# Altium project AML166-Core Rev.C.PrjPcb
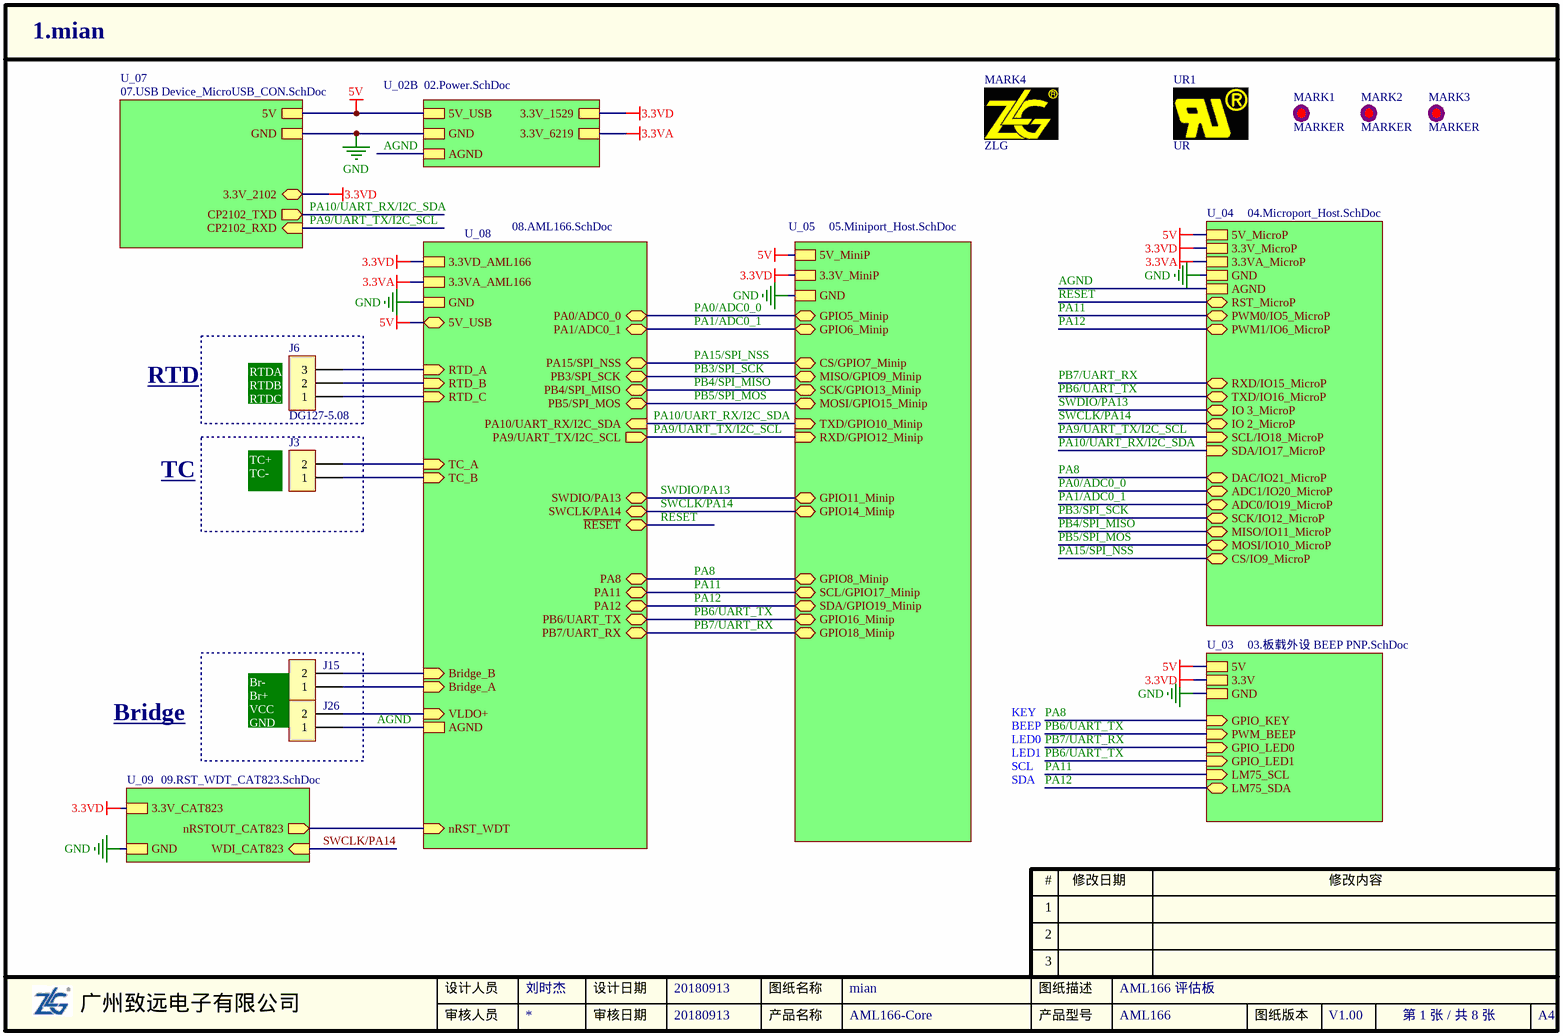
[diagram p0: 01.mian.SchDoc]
8 sheets, 138 parts. Net scope: hierarchical (ports join the sheet entries above them; power ports are global).
Board file: AML166-Core Rev.C.PcbDoc
Sheets:
  01.mian.SchDoc
    U_08 = 08.AML166.SchDoc
    U_05 = 05.Miniport_Host.SchDoc
    U_04 = 04.Microport_Host.SchDoc
    U_03 = 03.板载外设 BEEP PNP.SchDoc
    U_02B = 02.Power.SchDoc
    U_09 = 09.RST_WDT_CAT823.SchDoc
    U_07 = 07.USB Device_MicroUSB_CON.SchDoc

## Sheet 01.mian.SchDoc
size A4; Author: 刘时杰; CompanyName: 广州致远电子有限公司; DocumentNumber: 1; SheetNumber: 1; SheetTotal: 8; PageSetup: Record=PageOptions|CenterHorizontal=True|CenterVertical=True|PrintScale=1.00|XCorrection=1.00|YCorrection=1.00|PrintKind=0|BorderSize=5000000|LeftOffset=0|BottomOffset=0|Orientation=2|PaperLength=1000|PaperWidth=1000|Scale=100|PaperSource=7|PrintQuality=600|MediaType=1|DitherType=10|PaperKind=A4|PrintScaleMode=1; DesignDate: 20180913; CheckDate: 20180913; SheetName: mian; SheetVersion: V1.00; SheetDescription: AML166 评估板; ProductName: AML166-Core; ProductModel: AML166

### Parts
J3  (no value)  [CON508P810W130D15S-2DIP]
J6  DG127-5.08  [CON508P1524L810W110D15S-3DIP]
J15  (no value)  [CON508P810W130D15S-2DIP]
J26  (no value)  [CON508P810W130D15S-2DIP]
MARK1  MARKER  [MARKER-C-1.0M]  (no BOM)
MARK2  MARKER  [MARKER-C-1.0M]  (no BOM)
MARK3  MARKER  [MARKER-C-1.0M]  (no BOM)
MARK4  ZLG  [ZLG0.7]  (no BOM)
UR1  UR  [ZY_UR-3X2]  (no BOM)

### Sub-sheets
U_02B = 02.Power.SchDoc: GND, 5V_USB, 3.3V_1529, 3.3V_6219, AGND
U_03 = 03.板载外设 BEEP PNP.SchDoc: GND, 3.3V, PWM_BEEP (in), GPIO_LED0 (in), GPIO_LED1 (in), 5V, LM75_SCL (in), LM75_SDA (bidir), GPIO_KEY (in)
U_04 = 04.Microport_Host.SchDoc: GND, 3.3V_MicroP, AGND, 5V_MicroP, 3.3VA_MicroP, RXD/IO15_MicroP (bidir), TXD/IO16_MicroP (bidir), MOSI/IO10_MicroP (bidir), SCK/IO12_MicroP (bidir), MISO/IO11_MicroP (bidir), IO 3_MicroP (bidir), IO 2_MicroP (bidir), PWM1/IO6_MicroP (bidir), PWM0/IO5_MicroP (bidir), SDA/IO17_MicroP (in), SCL/IO18_MicroP (in), ADC1/IO20_MicroP (bidir), ADC0/IO19_MicroP (bidir), DAC/IO21_MicroP (bidir), RST_MicroP (bidir), CS/IO9_MicroP (bidir)
U_05 = 05.Miniport_Host.SchDoc: GND, 3.3V_MiniP, 5V_MiniP, MISO/GPIO9_Minip (bidir), GPIO5_Minip (bidir), MOSI/GPIO15_Minip (bidir), SCK/GPIO13_Minip (bidir), GPIO11_Minip (bidir), CS/GPIO7_Minip (bidir), GPIO14_Minip (bidir), GPIO6_Minip (bidir), RXD/GPIO12_Minip (in), TXD/GPIO10_Minip (in), GPIO8_Minip (bidir), GPIO16_Minip (bidir), SDA/GPIO19_Minip (bidir), SCL/GPIO17_Minip (bidir), GPIO18_Minip (bidir)
U_07 = 07.USB Device_MicroUSB_CON.SchDoc: 5V, GND, CP2102_TXD (out), CP2102_RXD (in), 3.3V_2102
U_08 = 08.AML166.SchDoc: nRST_WDT (in), 3.3VD_AML166, PA10/UART_RX/I2C_SDA (in), PA15/SPI_NSS (bidir), PA0/ADC0_0 (bidir), PA1/ADC0_1 (bidir), PA9/UART_TX/I2C_SCL (out), PB3/SPI_SCK (bidir), PB5/SPI_MOS (bidir), PA11 (bidir), PA12 (bidir), PB7/UART_RX (bidir), PB4/SPI_MISO (bidir), PA8 (bidir), PB6/UART_TX (bidir), GND, RTD_A (in), RTD_B (in), RTD_C (in), TC_A (in), TC_B (in), AGND, SWDIO/PA13 (bidir), SWCLK/PA14 (bidir), ~{RESET} (bidir), 3.3VA_AML166, Bridge_A (in), Bridge_B (in), VLDO+ (in), 5V_USB
U_09 = 09.RST_WDT_CAT823.SchDoc: GND, 3.3V_CAT823, WDI_CAT823 (in), nRSTOUT_CAT823 (out)

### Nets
3.3VA: sheet U_08/3.3VA_AML166, sheet U_04/3.3VA_MicroP, sheet U_02B/3.3V_6219  [project net 3.3V_6219]
3.3VD: sheet U_08/3.3VD_AML166, sheet U_05/3.3V_MiniP, sheet U_04/3.3V_MicroP, sheet U_03/3.3V, sheet U_02B/3.3V_1529, sheet U_09/3.3V_CAT823, sheet U_07/3.3V_2102  [project net 3.3V]
5V: sheet U_08/5V_USB, sheet U_05/5V_MiniP, sheet U_04/5V_MicroP, sheet U_03/5V, sheet U_02B/5V_USB, sheet U_07/5V
AGND: J26.1 ; sheet U_08/GND, sheet U_08/AGND, sheet U_05/GND, sheet U_04/GND, sheet U_04/AGND, sheet U_03/GND, sheet U_02B/GND, sheet U_02B/AGND, sheet U_09/GND, sheet U_07/GND  [also labelled GND]
ADC1_0: J15.1 ; sheet U_08/Bridge_A
ADC1_1: J15.2 ; sheet U_08/Bridge_B
nRST_WDT: sheet U_08/nRST_WDT, sheet U_09/nRSTOUT_CAT823
PA0/ADC0_0: sheet U_08/PA0/ADC0_0, sheet U_05/GPIO5_Minip, sheet U_04/ADC1/IO20_MicroP  [project net ADC1/IO20_MicroP]
PA1/ADC0_1: sheet U_08/PA1/ADC0_1, sheet U_05/GPIO6_Minip, sheet U_04/ADC0/IO19_MicroP  [project net ADC0/IO19_MicroP]
PA8: sheet U_08/PA8, sheet U_05/GPIO8_Minip, sheet U_04/DAC/IO21_MicroP, sheet U_03/GPIO_KEY  [project net DAC/IO21_MicroP]
PA9/UART_TX/I2C_SCL: sheet U_08/PA9/UART_TX/I2C_SCL, sheet U_05/RXD/GPIO12_Minip, sheet U_04/SCL/IO18_MicroP, sheet U_07/CP2102_RXD
PA10/UART_RX/I2C_SDA: sheet U_08/PA10/UART_RX/I2C_SDA, sheet U_05/TXD/GPIO10_Minip, sheet U_04/SDA/IO17_MicroP, sheet U_07/CP2102_TXD
PA11: sheet U_08/PA11, sheet U_05/SCL/GPIO17_Minip, sheet U_04/PWM0/IO5_MicroP, sheet U_03/LM75_SCL  [project net LM75_SCL]
PA12: sheet U_08/PA12, sheet U_05/SDA/GPIO19_Minip, sheet U_04/PWM1/IO6_MicroP, sheet U_03/LM75_SDA  [project net LM75_SDA]
PA15/SPI_NSS: sheet U_08/PA15/SPI_NSS, sheet U_05/CS/GPIO7_Minip, sheet U_04/CS/IO9_MicroP  [project net CS/GPIO7_Minip]
PB3/SPI_SCK: sheet U_08/PB3/SPI_SCK, sheet U_05/MISO/GPIO9_Minip, sheet U_04/SCK/IO12_MicroP  [project net MISO/GPIO9_Minip]
PB4/SPI_MISO: sheet U_08/PB4/SPI_MISO, sheet U_05/SCK/GPIO13_Minip, sheet U_04/MISO/IO11_MicroP  [project net MISO/IO11_MicroP]
PB5/SPI_MOS: sheet U_08/PB5/SPI_MOS, sheet U_05/MOSI/GPIO15_Minip, sheet U_04/MOSI/IO10_MicroP  [project net MOSI/GPIO15_Minip]
PB6/UART_TX: sheet U_08/PB6/UART_TX, sheet U_05/GPIO16_Minip, sheet U_04/TXD/IO16_MicroP, sheet U_03/PWM_BEEP, sheet U_03/GPIO_LED1  [project net GPIO16_Minip]
PB7/UART_RX: sheet U_08/PB7/UART_RX, sheet U_05/GPIO18_Minip, sheet U_04/RXD/IO15_MicroP, sheet U_03/GPIO_LED0  [project net GPIO18_Minip]
~{RESET}: sheet U_08/~{RESET}, sheet U_04/RST_MicroP
RTD_A: J6.3 ; sheet U_08/RTD_A
RTD_B: J6.2 ; sheet U_08/RTD_B
RTD_C: J6.1 ; sheet U_08/RTD_C
SWCLK/PA14: sheet U_08/SWCLK/PA14, sheet U_05/GPIO14_Minip, sheet U_04/IO 2_MicroP, sheet U_09/WDI_CAT823  [project net GPIO14_Minip]
SWDIO/PA13: sheet U_08/SWDIO/PA13, sheet U_05/GPIO11_Minip, sheet U_04/IO 3_MicroP  [project net GPIO11_Minip]
TC_A: J3.2 ; sheet U_08/TC_A
TC_B: J3.1 ; sheet U_08/TC_B
VLDO: J26.2 ; sheet U_08/VLDO+

Not connected (* = marked no-connect by the designer): MARK1 0; MARK2 0; MARK3 0

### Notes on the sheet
- RTD
- (near J6) RTDA
  RTDB
  RTDC
- TC
- (near J3) TC+
  TC-
- KEY
- Bridge
- Br-
  Br+
  VCC
  GND
- BEEP
- LED0
- LED1
- SCL
- SDA

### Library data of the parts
J3 J15 J26 = 1.10.06.0070: DG127-5.08-02P-14-00AH,180°,绿色,DEGSON,RoHS; 名称: 端子; 贴片和直插: THT; PCB备注: xhm-lq-wyy-150126; 器件优选方案: 正常状态，可以选用
J6 = 19.04.00251: DG127-5.08-03P-14-00AH,180°,绿色,THT; 名称: 端子; PCB备注: 180925 yyf

## Sheet 08.AML166.SchDoc
size A3; CheckedBy: <审核人员>; Author: 刘时杰; DocumentNumber: 7; SheetNumber: 7; SheetTotal: 8; PageSetup: Record=PageOptions|CenterHorizontal=True|CenterVertical=True|PrintScale=1.00|XCorrection=1.00|YCorrection=1.00|PrintKind=0|BorderSize=5000000|LeftOffset=0|BottomOffset=0|Orientation=2|PaperLength=1000|PaperWidth=1000|Scale=100|PaperSource=7|PrintQuality=600|MediaType=1|DitherType=10|PaperKind=A4|PrintScaleMode=1; DesignDate: 20180913; CheckDate: <审核日期>; SheetName: AML166_ADC24; SheetVersion: <图纸版本>; SheetDescription: AML166评估24位ADC性能电路; ProductName: AML166; ProductModel: AML166-Core
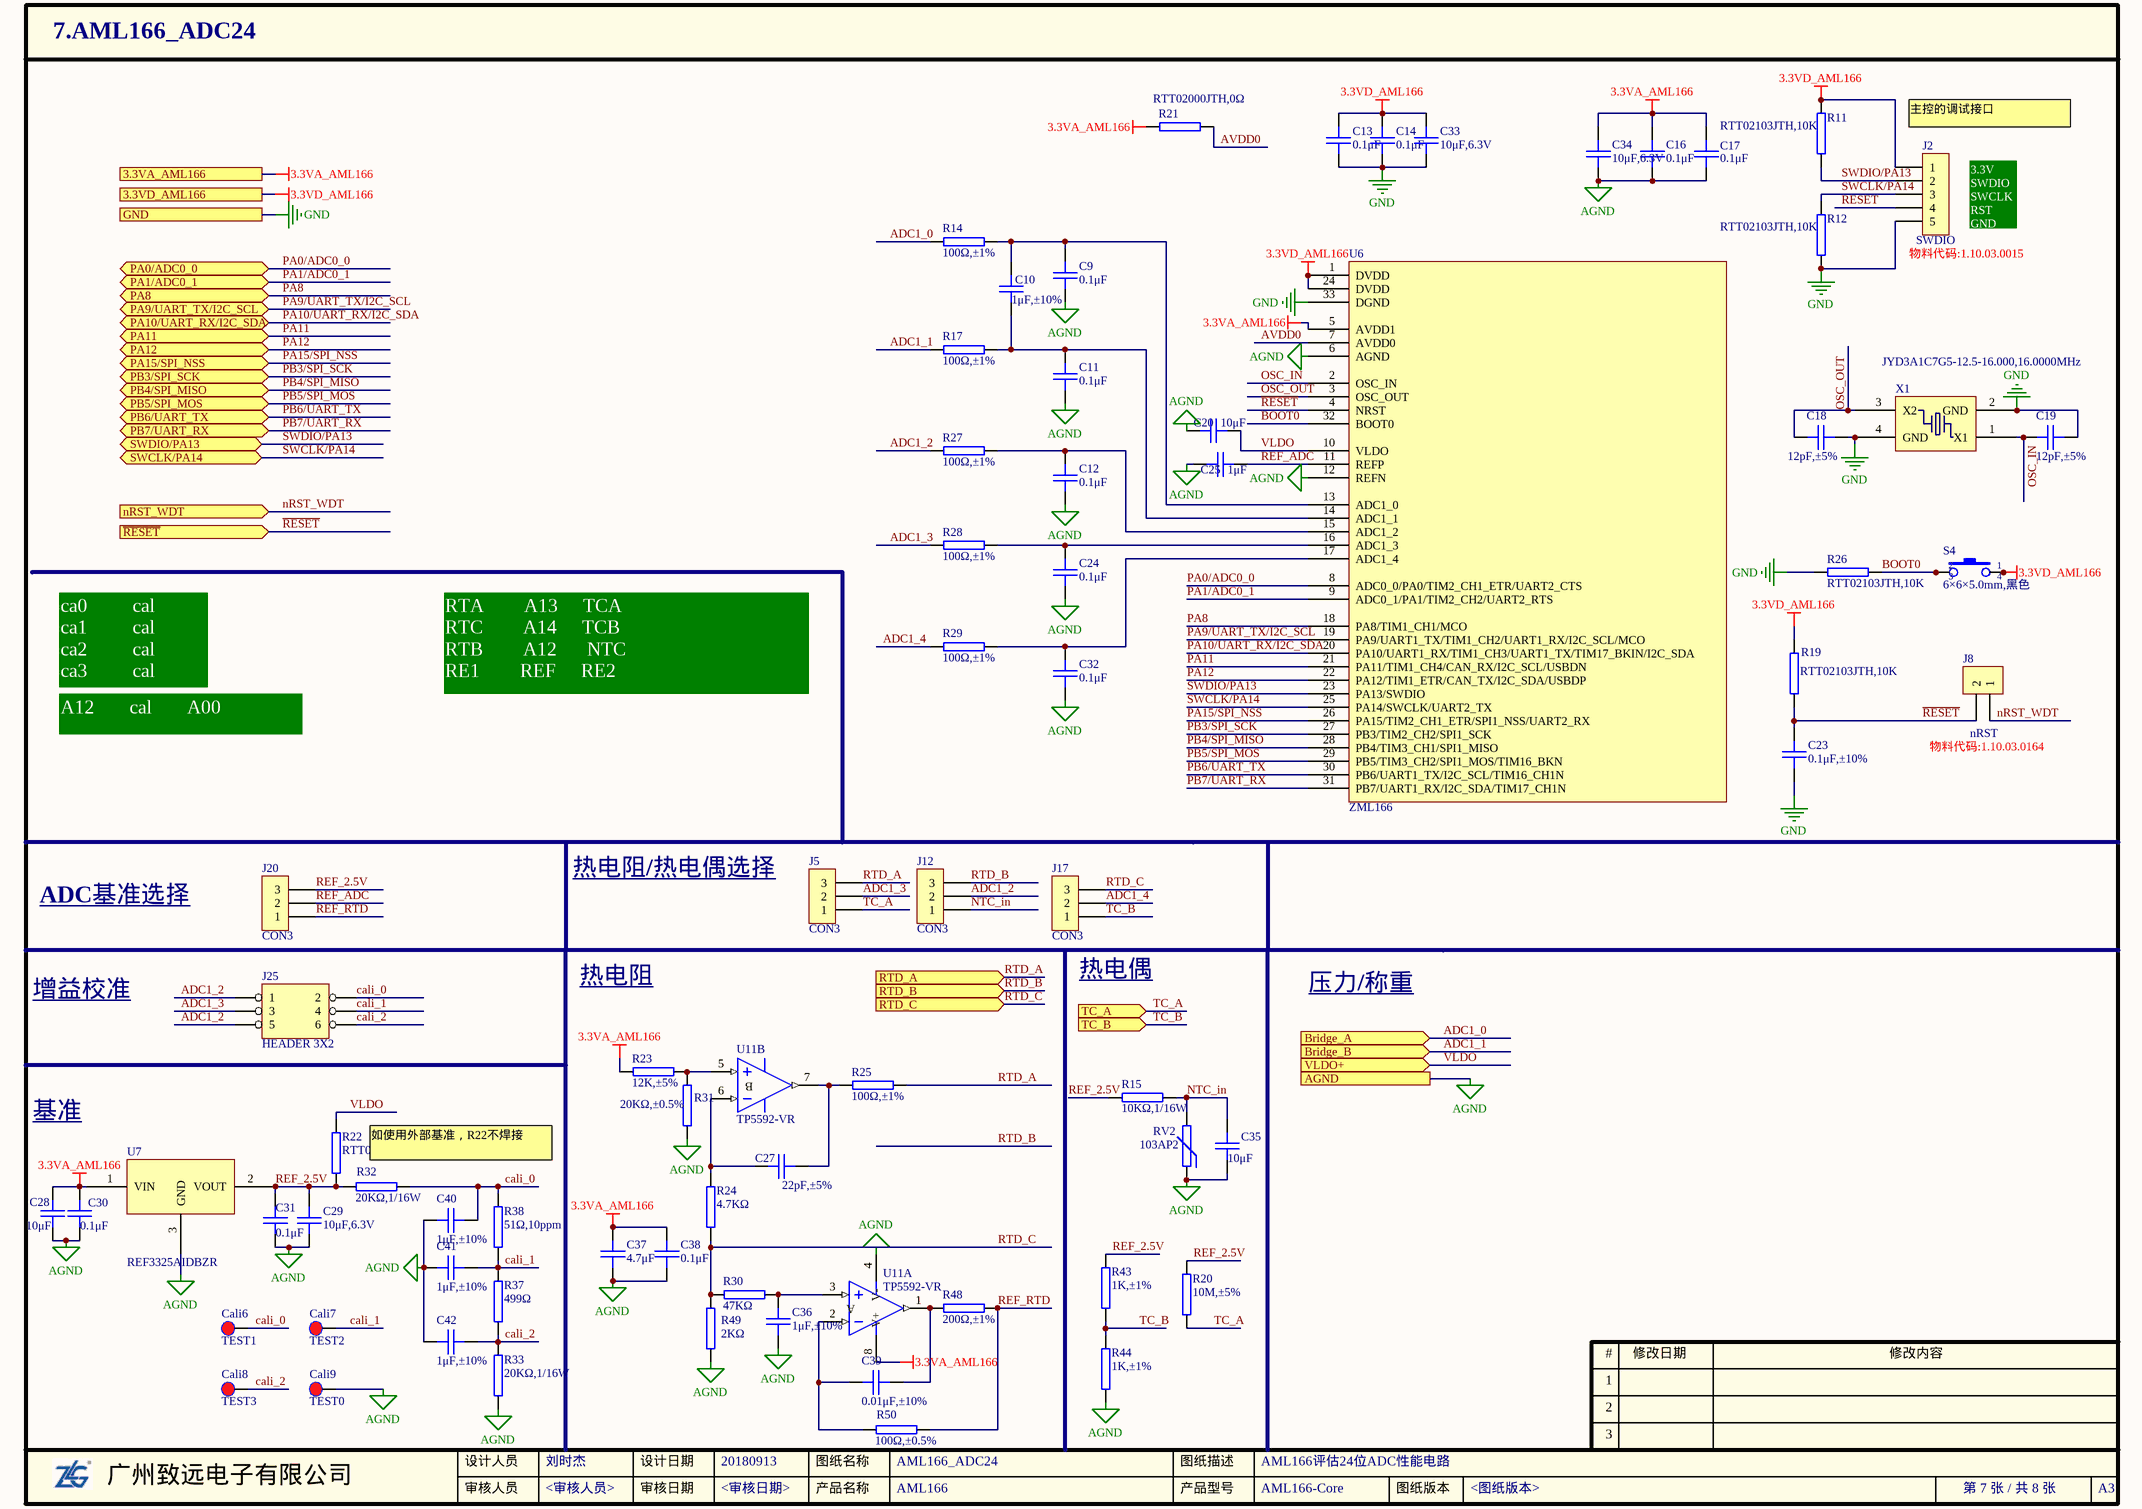
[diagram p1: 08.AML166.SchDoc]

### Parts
C9  0.1μF  [0402C]
C10  1μF,±10%  [0402C]
C11  0.1μF  [0402C]
C12  0.1μF  [0402C]
C13  0.1μF  [0402C]
C14  0.1μF  [0402C]
C16  0.1μF  [0402C]
C17  0.1μF  [0402C]
C18  12pF,±5%  [0402C]
C19  12pF,±5%  [0402C]
C20  10μF  [0603C]
C23  0.1μF,±10%  [0402C]
C24  0.1μF  [0402C]
C25  1μF  [0402C]
C27  22pF,±5%  [0402C]
C28  10μF  [0603C]
C29  10μF,6.3V  [0603C]
C30  0.1μF  [0402C]
C31  0.1μF  [0402C]
C32  0.1μF  [0402C]
C33  10μF,6.3V  [0603C]
C34  10μF,6.3V  [0603C]
C35  10μF  [0603C]
C36  1μF,±10%  [0402C]
C37  4.7μF  [0402C]
C38  0.1μF  [0402C]
C39  0.01μF,±10%  [0402C]
C40  1μF,±10%  [0402C]
C41  1μF,±10%  [0402C]
C42  1μF,±10%  [0402C]
Cali6  TEST1  [PAD-25/40]  (no BOM)
Cali7  TEST2  [PAD-25/40]  (no BOM)
Cali8  TEST3  [PAD-25/40]  (no BOM)
Cali9  TEST0  [PAD-25/40]  (no BOM)
J2  SWDIO  [SIP-5-2.54-6.0-R90]
J5  CON3  [SIP-3-2.54]
J8  nRST  [SIP-2-2.54]
J12  CON3  [SIP-3-2.54]
J17  CON3  [SIP-3-2.54]
J20  CON3  [SIP-3-2.54]
J25  HEADER 3X2  [IDC-6-2.54]
R11  RTT02103JTH,10K  [0402R]
R12  RTT02103JTH,10K  [0402R]
R14  100Ω,±1%  [0402R]
R15  10KΩ,1/16W  [0603R]
R17  100Ω,±1%  [0402R]
R19  RTT02103JTH,10K  [0402R]
R20  10M,±5%  [0402R]
R21  RTT02000JTH,0Ω  [0402R]
R22  RTT02000JTH,0Ω  [0402R]  (no BOM)
R23  12K,±5%  [0402R]
R24  4.7KΩ  [0603R]
R25  100Ω,±1%  [0402R]
R26  RTT02103JTH,10K  [0402R]
R27  100Ω,±1%  [0402R]
R28  100Ω,±1%  [0402R]
R29  100Ω,±1%  [0402R]
R30  47KΩ  [0603R]
R31  20KΩ,±0.5%  [0402R]
R32  20KΩ,1/16W  [0603R]
R33  20KΩ,1/16W  [0603R]
R37  499Ω  [0603R]
R38  51Ω,10ppm  [0603R]
R43  1K,±1%  [0402R]
R44  1K,±1%  [0402R]
R48  200Ω,±1%  [0402R]
R49  2KΩ  [0603R]
R50  100Ω,±0.5%  [0402R]
RV2  103AP2  [RESRR254W35L380T260H850P]
S4  value 6×6×5.0mm,黑色  [KEY-6S]  (hidden comment: SW-PB4P)
U6  ZML166  [QFN50P500X500X85-33N]
U7  REF3325AIDBZR  [SOT-23]
U11  TP5592-VR  [SOP65P490X120-8N]  (parts A,B of 2)
X1  JYD3A1C7G5-12.5-16.000,16.0000MHz  [OSCCC250X320X80-4N]

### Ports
3.3VA_AML166, 3.3VD_AML166, AGND, Bridge_A (in), Bridge_B (in), GND, nRST_WDT (in), PA0/ADC0_0 (bidir), PA1/ADC0_1 (bidir), PA8 (bidir), PA9/UART_TX/I2C_SCL (bidir), PA10/UART_RX/I2C_SDA (bidir), PA11 (bidir), PA12 (bidir), PA15/SPI_NSS (bidir), PB3/SPI_SCK (bidir), PB4/SPI_MISO (bidir), PB5/SPI_MOS (bidir), PB6/UART_TX (bidir), PB7/UART_RX (bidir), RTD_A (in), RTD_B (in), RTD_C (in), SWCLK/PA14 (bidir), SWDIO/PA13 (bidir), TC_A (in), TC_B (in), VLDO+ (in), ~{RESET} (in)

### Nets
3.3VA_AML166: C16.1 C17.1 C28.2 C30.1 C34.2 C37.1 C38.1 R21.1 R23.1 U6.5(AVDD1) U7.1(VIN) U11.8(V+) ; port 3.3VA_AML166  [project net 3.3V_6219]
3.3VD_AML166: C13.1 C14.1 C33.2 J2.1 R11.2 R19.1 S4.1 S4.4 U6.1(DVDD) U6.24(DVDD) ; port 3.3VD_AML166  [project net 3.3V]
AGND: C9.2 C11.2 C12.2 C13.2 C14.2 C16.2 C17.2 C18.1 C19.2 C20.2 C23.2 C24.2 C25.1 C28.1 C29.1 C30.2 C31.2 C32.2 C33.1 C34.1 C35.1 C36.2 C37.2 C38.2 C40.1 C41.1 C42.1 Cali9.1 J2.5 R12.1 R26.2 R31.1 R33.2 R44.2 R49.1 RV2.1 U6.6(AGND) U6.12(REFN) U6.33(DGND) U7.3(GND) U11.4(V-) X1.2(GND) X1.4(GND) ; port GND, port AGND  [also labelled GND]
ADC1_0: R14.1 ; port Bridge_A
ADC1_1: R17.1 ; port Bridge_B
ADC1_2: J12.2 J25.1 J25.5 R27.1
ADC1_3: J5.2 J25.3 R28.1
ADC1_4: J17.2 R29.1
AVDD0: R21.2 U6.7(AVDD0)
BOOT0: R26.1 S4.2 S4.3 U6.32(BOOT0)
cali_0: C40.2 Cali6.1 J25.2 R32.1 R38.1
cali_1: C41.2 Cali7.1 J25.4 R37.2 R38.2
cali_2: C42.2 Cali8.1 J25.6 R33.1 R37.1
nRST_WDT: J8.1 ; port nRST_WDT
NTC_in: C35.2 J12.1 R15.2 RV2.2
OSC_IN: C19.1 U6.2(OSC_IN) X1.1(X1)
OSC_OUT: C18.2 U6.3(OSC_OUT) X1.3(X2)
PA0/ADC0_0: U6.8(ADC0_0/PA0/TIM2_CH1_ETR/UART2_CTS) ; port PA0/ADC0_0  [project net ADC1/IO20_MicroP]
PA1/ADC0_1: U6.9(ADC0_1/PA1/TIM2_CH2/UART2_RTS) ; port PA1/ADC0_1  [project net ADC0/IO19_MicroP]
PA8: U6.18(PA8/TIM1_CH1/MCO) ; port PA8  [project net DAC/IO21_MicroP]
PA9/UART_TX/I2C_SCL: U6.19(PA9/UART1_TX/TIM1_CH2/UART1_RX/I2C_SCL/MCO) ; port PA9/UART_TX/I2C_SCL
PA10/UART_RX/I2C_SDA: U6.20(PA10/UART1_RX/TIM1_CH3/UART1_TX/TIM17_BKIN/I2C_SDA) ; port PA10/UART_RX/I2C_SDA
PA11: U6.21(PA11/TIM1_CH4/CAN_RX/I2C_SCL/USBDN) ; port PA11  [project net LM75_SCL]
PA12: U6.22(PA12/TIM1_ETR/CAN_TX/I2C_SDA/USBDP) ; port PA12  [project net LM75_SDA]
PA15/SPI_NSS: U6.26(PA15/TIM2_CH1_ETR/SPI1_NSS/UART2_RX) ; port PA15/SPI_NSS  [project net CS/GPIO7_Minip]
PB3/SPI_SCK: U6.27(PB3/TIM2_CH2/SPI1_SCK) ; port PB3/SPI_SCK  [project net MISO/GPIO9_Minip]
PB4/SPI_MISO: U6.28(PB4/TIM3_CH1/SPI1_MISO) ; port PB4/SPI_MISO  [project net MISO/IO11_MicroP]
PB5/SPI_MOS: U6.29(PB5/TIM3_CH2/SPI1_MOS/TIM16_BKN) ; port PB5/SPI_MOS  [project net MOSI/GPIO15_Minip]
PB6/UART_TX: U6.30(PB6/UART1_TX/I2C_SCL/TIM16_CH1N) ; port PB6/UART_TX  [project net GPIO16_Minip]
PB7/UART_RX: U6.31(PB7/UART1_RX/I2C_SDA/TIM17_CH1N) ; port PB7/UART_RX  [project net GPIO18_Minip]
~{RESET}: C23.1 J2.4 J8.2 R19.2 U6.4(NRST) ; port ~{RESET}
REF_2.5V: C29.2 C31.1 J20.3 R15.1 R20.2 R22.1 R32.2 R43.2 U7.2(VOUT)
REF_ADC: C25.2 J20.2 U6.11(REFP)
REF_RTD: J20.1 R48.2 R50.1
RTD_A: J5.3 R25.2 ; port RTD_A
RTD_B: J12.3 ; port RTD_B
RTD_C: J17.3 R24.1 R30.1 R49.2 ; port RTD_C
SWCLK/PA14: J2.3 R12.2 U6.25(PA14/SWCLK/UART2_TX) ; port SWCLK/PA14  [project net GPIO14_Minip]
SWDIO/PA13: J2.2 R11.1 U6.23(PA13/SWDIO) ; port SWDIO/PA13  [project net GPIO11_Minip]
TC_A: J5.1 R20.1 ; port TC_A
TC_B: J17.1 R43.1 R44.1 ; port TC_B
VLDO: C20.1 R22.2 U6.10(VLDO) ; port VLDO+
NetC9_1: C9.1 C10.1 R14.2 U6.13(ADC1_0)
NetC10_2: C10.2 C11.1 R17.2 U6.14(ADC1_1)
NetC12_1: C12.1 R27.2 U6.15(ADC1_2)
NetC24_1: C24.1 R28.2 U6.16(ADC1_3)
NetC27_1: C27.1 R24.2 U11.6(IN-)
NetC27_2: C27.2 R25.1 U11.7(OUT)
NetC32_1: C32.1 R29.2 U6.17(ADC1_4)
NetC36_1: C36.1 R30.2 U11.3(IN+)
NetC39_1: C39.1 R50.2 U11.2(IN-)
NetC39_2: C39.2 R48.1 U11.1(OUT)
NetR23_2: R23.2 R31.2 U11.5(IN+)

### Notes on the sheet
- (near J2) 主控的调试接口
- (near J2) 3.3V
  SWDIO
  SWCLK
  RST
  GND
- (near J2) 物料代码:1.10.03.0015
- ca0         cal
  ca1         cal
  ca2         cal
  ca3         cal
- RTA        A13     TCA
  RTC        A14     TCB
  RTB        A12      NTC
  RE1        REF     RE2
- A12       cal       A00
- (near J8) 物料代码:1.10.03.0164
- ADC基准选择
- 热电阻/热电偶选择
- 热电阻
- (near J17) 热电偶
- 压力/称重
- 增益校准
- 基准
- 如使用外部基准，R22不焊接

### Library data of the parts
C9 C11-C14 C16 C17 C24 C30-C32 C38 = 1.02.17.0118: GCM155R71E104KE02D,0.1μF,±10%,25V,X7R,0402,muRata,RoHS; 名称: 电容; 封装: 0402; 贴片和直插: SMT; PCB备注: 161012yjh; 器件优选方案: 正常状态，可以选用
C10 C25 C36 C40-C42 = 1.02.17.0092: GRM155R61C105KA12D,1μF,±10% ,16V,X5R,0402,muRata,RoHS; 名称: 电容; 封装: 0402; 贴片和直插: SMT; PCB备注: 无数据手册，依据采购部提供的信息添加的封装。; 器件优选方案: 正常状态，可以选用
C18 C19 = 1.02.17.0018: GRM1555C1H120JA01D,12pF,±5%,50V,C0G,0402,muRata,RoHS; 名称: 电容; 封装: 0402; 设备封装名称: C0402_12PF_COG_50V_5%; 贴片和直插: SMT; 器件优选方案: 正常状态，可以选用
C20 C28 C29 C33-C35 = 1.02.01.0065: 10μF,6.3V,X5R,GRM188R60J106M****,0603,Murata,RoHS; 名称: 电容; 封装: 0603; 贴片和直插: SMT; 器件优选方案: 正常状态，可以选用
C23 = 1.02.17.0006: GRM155R71C104KA88D,0.1μF,±10%,16V,X7R,0402,muRata,RoHS; 名称: 电容; 封装: 0402; 设备封装名称: C0402_0.1uF_X7R_16V_10%; 贴片和直插: SMT; 器件优选方案: 正常状态，可以选用
C27 = 1.02.17.0036: GRM1555C1H220JA01D,22pF,±5%,50V,C0G,0402,muRata,RoHS; 名称: 电容; 封装: 0402; 设备封装名称: C0402_22PF_NPO_50V_5%; 贴片和直插: SMT; 器件优选方案: 正常状态，可以选用
C37 = 1.02.17.0073: GRM155R60J475ME87D,4.7μF,±20%,6.3V,X5R,0402,muRata,RoHS; 名称: 电容; 封装: 0402; 贴片和直插: SMT; 器件优选方案: 正常状态，可以选用
C39 = 1.02.17.0019: GRM155R71H103KA88D,0.01μF,±10%,50V,X7R,0402,muRata,RoHS; 名称: 电容; 封装: 0402; 设备封装名称: C0402_0.01uF_X7R_50V_10%; 贴片和直插: SMT; 器件优选方案: 正常状态，可以选用
Cali6-Cali9 = TEST-DOT
J2 = CON5: Connector; 物料代码: 1.10.03.0015
J5 J12 J17 J20 = CON3: Connector
J8 = CON2: Connector; 物料代码: 1.10.03.0164
R11 R12 R19 R26 = 1.01.17.0006: RTT02103JTH,10K,±5%,0402,RALEC,RoHS; 名称: 电阻; 封装: 0402; 设备封装名称: R0402_10K; 贴片和直插: SMT; 器件优选方案: 正常状态，可以选用
R14 R17 R25 R27-R29 = 1.01.17.0029: 100Ω,±1%,0402,RALEC,RoHS; 名称: 电阻; 封装: 0402; 设备封装名称: R0402_100R_1%; 贴片和直插: SMT; 器件优选方案: 正常状态，可以选用
R15 = 1.01.01.0192: 10KΩ,1/16W,10PPM/℃,±0.1%,0603,Viking,RoHS; 名称: 电阻; 封装: 0603; 设备封装名称: R0603_10K_0.1%; 贴片和直插: SMT; 器件优选方案: 临时/偏门物料/不主推物料，谨慎选用
R20 = 1.01.17.0005: 10M,±5%,0402,RALEC,RoHS; 名称: 电阻; 封装: 0402; 设备封装名称: R0402_10M; 贴片和直插: SMT; 器件优选方案: 正常状态，可以选用
R21 R22 = 1.01.17.0004: RTT02000JTH,0Ω,±5%,0402,RALEC,RoHS; 名称: 电阻; 封装: 0402; 设备封装名称: R0402_0R; 贴片和直插: SMT; 器件优选方案: 正常状态，可以选用
R23 = 1.01.17.0035: 12K,±5%,0402,RALEC,RoHS; 名称: 电阻; 封装: 0402; 设备封装名称: R0402_12K; 贴片和直插: SMT; 器件优选方案: 正常状态，可以选用
R24 = 1.01.01.0045: 4.7KΩ,0603,*,RoHS; 名称: 电阻; 封装: 0603; 设备封装名称: R0603_4.7K; 厂商: Ralec; 贴片和直插: SMT; 器件优选方案: 正常状态，可以选用
R30 = 1.01.01.0060: 47KΩ,0603,*,RoHS; 名称: 电阻; 封装: 0603; 设备封装名称: R0603_47K; 厂商: Ralec; 贴片和直插: SMT; 器件优选方案: 正常状态，可以选用
R31 = 1.01.17.0053: 20KΩ,±0.5%,0402,RoHS; 名称: 电阻; 封装: 0402; 设备封装名称: R0402_20K_0.5%; 厂商: Ralec; 贴片和直插: SMT; 器件优选方案: 正常状态，可以选用
R32 R33 = 1.01.01.0207: 20KΩ,1/16W,10PPM/℃,±0.1%,0603,Viking,RoHS; 名称: 电阻; 封装: 0603; 贴片和直插: SMT; 器件优选方案: 临时/偏门物料/不主推物料，谨慎选用
R37 = 1.01.01.0155: 499Ω,RN731JTTD,4990B10,0603,KOA,RoHS; 名称: 电阻; 封装: 0603; 设备封装名称: R0603_499R_0.1%; 贴片和直插: SMT; 器件优选方案: 临时/偏门物料/不主推物料，谨慎选用
R38 = 1.01.01.0215: 51Ω,10ppm,±0.1%,AR03BTB0510,0603,Viking,RoHS; 名称: 电阻; 封装: 0603; 贴片和直插: SMT; 器件优选方案: 临时/偏门物料/不主推物料，谨慎选用
R43 R44 = 1.01.17.0016: 1K,±1%,0402,RALEC,RoHS; 名称: 电阻; 封装: 0402; 设备封装名称: R0402_1K_1%; 贴片和直插: SMT; 器件优选方案: 正常状态，可以选用
R48 = 1.01.17.0073: 200Ω,±1%,0402,RoHS; 名称: 电阻; 封装: 0402; 设备封装名称: R0402_200R_1%; 厂商: Ralec; 贴片和直插: SMT; 器件优选方案: 正常状态，可以选用
R49 = 1.01.01.0157: 2KΩ,RN731JTTD,2001B10,0603,KOA,RoHS; 名称: 电阻; 封装: 0603; 设备封装名称: R0603_2K_0.1%; 贴片和直插: SMT; 器件优选方案: 临时/偏门物料/不主推物料，谨慎选用
R50 = 1.01.17.0052: 100Ω,±0.5%,0402,RoHS; 名称: 电阻; 封装: 0402; 设备封装名称: R0402_100R_0.5%; 厂商: Ralec; 贴片和直插: SMT; 器件优选方案: 正常状态，可以选用
RV2 = 1.01.14.0020: 103AP2,SIP,semitec,RoHS; 名称: 热敏电阻(临时); 贴片和直插: THT; PCB备注: 171205CZY; 器件优选方案: 临时/偏门物料/不主推物料，谨慎选用
S4 = 1.09.01.0003: 6×6×5.0mm,黑色,SMD,,*; 名称: 轻触按键; 贴片和直插: SMT
U7 = 1.05.10.0334: REF3325AIDBZR,SOT-23,TI; 名称: 集成电路; 设备封装名称: SOT-23_REF3325AIDBZR; 贴片和直插: SMT; 器件优选方案: 量产物料,优先选用
U11 = 1.05.20.0102: TP5592-VR,MSOP-8,3PEAK,RoHS; 名称: 集成电路(临时); 贴片和直插: SMT; PCB备注: 170810lmd; 器件优选方案: 临时/偏门物料/不主推物料，谨慎选用
X1 = 1.07.03.0077: JYD3A1C7G5-12.5-16.000,16.0000MHz,±10ppm,12.5pF,-40~85℃,SMD3225,JYEG,RoHS; 名称: 晶体; 贴片和直插: SMT; PCB备注: 151225lmd171128ZW; 器件优选方案: 正常状态，可以选用

## Sheet 05.Miniport_Host.SchDoc
size A4; CheckedBy: <审核日期>; Author: 刘时杰; CompanyName: 广州致远电子有限公司; DocumentNumber: 5; SheetNumber: 5; SheetTotal: 8; PageSetup: Record=PageOptions|CenterHorizontal=True|CenterVertical=True|PrintScale=1.00|XCorrection=1.00|YCorrection=1.00|PrintKind=0|BorderSize=5000000|LeftOffset=0|BottomOffset=0|Orientation=2|PaperLength=1000|PaperWidth=1000|Scale=100|PaperSource=7|PrintQuality=600|MediaType=1|DitherType=10|PaperKind=A4|PrintScaleMode=1; DesignDate: 20180913; CheckDate: <审核人员>; SheetName: MiniPort接口; SheetVersion: V1.01; SheetDescription: MiniPort接口; productModel: AML166-Core; productName: AML166评估板
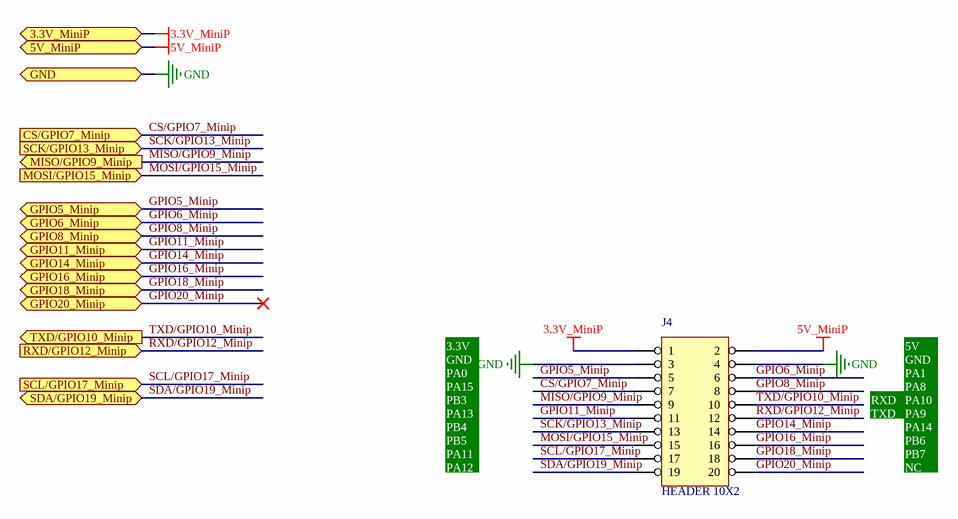
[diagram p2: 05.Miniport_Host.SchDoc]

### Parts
J4  HEADER 10X2  [IDC-20-2.54-R90]

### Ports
3.3V_MiniP, 5V_MiniP, CS/GPIO7_Minip (in), GND, GPIO5_Minip (bidir), GPIO6_Minip (bidir), GPIO8_Minip (bidir), GPIO11_Minip (bidir), GPIO14_Minip (bidir), GPIO16_Minip (bidir), GPIO18_Minip (bidir), GPIO20_Minip (bidir), MISO/GPIO9_Minip (out), MOSI/GPIO15_Minip (in), RXD/GPIO12_Minip (in), SCK/GPIO13_Minip (in), SCL/GPIO17_Minip (in), SDA/GPIO19_Minip (bidir), TXD/GPIO10_Minip (out)

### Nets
3.3V_MiniP: J4.1 ; port 3.3V_MiniP  [project net 3.3V]
5V_MiniP: J4.2 ; port 5V_MiniP  [project net 5V]
GND: J4.3 J4.4 ; port GND  [project net AGND]
CS/GPIO7_Minip: J4.7 ; port CS/GPIO7_Minip
GPIO5_Minip: J4.5 ; port GPIO5_Minip  [project net ADC1/IO20_MicroP]
GPIO6_Minip: J4.6 ; port GPIO6_Minip  [project net ADC0/IO19_MicroP]
GPIO8_Minip: J4.8 ; port GPIO8_Minip  [project net DAC/IO21_MicroP]
GPIO11_Minip: J4.11 ; port GPIO11_Minip
GPIO14_Minip: J4.14 ; port GPIO14_Minip
GPIO16_Minip: J4.16 ; port GPIO16_Minip
GPIO18_Minip: J4.18 ; port GPIO18_Minip
GPIO20_Minip: J4.20 ; port GPIO20_Minip
MISO/GPIO9_Minip: J4.9 ; port MISO/GPIO9_Minip
MOSI/GPIO15_Minip: J4.15 ; port MOSI/GPIO15_Minip
RXD/GPIO12_Minip: J4.12 ; port RXD/GPIO12_Minip  [project net PA9/UART_TX/I2C_SCL]
SCK/GPIO13_Minip: J4.13 ; port SCK/GPIO13_Minip  [project net MISO/IO11_MicroP]
SCL/GPIO17_Minip: J4.17 ; port SCL/GPIO17_Minip  [project net LM75_SCL]
SDA/GPIO19_Minip: J4.19 ; port SDA/GPIO19_Minip  [project net LM75_SDA]
TXD/GPIO10_Minip: J4.10 ; port TXD/GPIO10_Minip  [project net PA10/UART_RX/I2C_SDA]

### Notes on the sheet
- TXD
- RXD
- 3.3V
  GND
  PA0
  PA15
  PB3
  PA13
  PB4
  PB5
  PA11
  PA12
- 5V
  GND
  PA1
  PA8
  PA10
  PA9
  PA14
  PB6
  PB7
  NC

## Sheet 04.Microport_Host.SchDoc
size A4; CheckedBy: <审核日期>; Author: 刘时杰; CompanyName: 广州致远电子有限公司; DocumentNumber: 4; SheetNumber: 4; SheetTotal: 8; PageSetup: Record=PageOptions|CenterHorizontal=True|CenterVertical=True|PrintScale=1.00|XCorrection=1.00|YCorrection=1.00|PrintKind=0|BorderSize=5000000|LeftOffset=0|BottomOffset=0|Orientation=2|PaperLength=1000|PaperWidth=1000|Scale=100|PaperSource=7|PrintQuality=600|MediaType=1|DitherType=10|PaperKind=A4|PrintScaleMode=1; DesignDate: 20180913; CheckDate: <审核人员>; SheetName: MicroPort接口; SheetVersion: V1.01; SheetDescription: MicroPort接口; productModel: AML166-Core; productName: AML166评估板
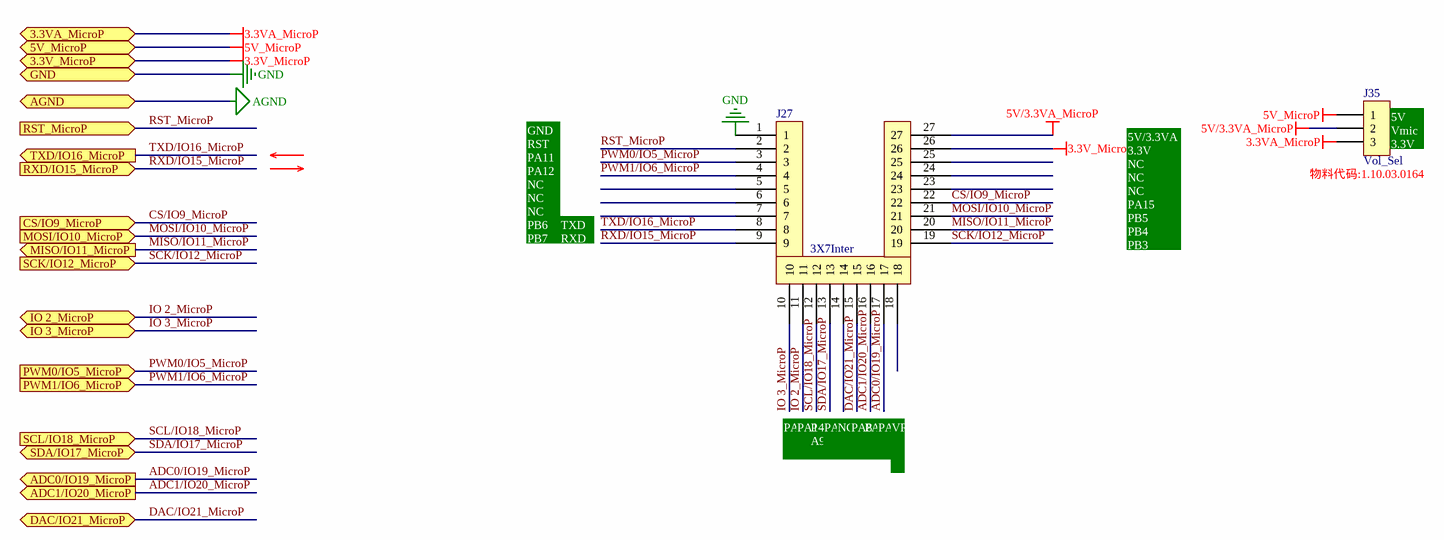
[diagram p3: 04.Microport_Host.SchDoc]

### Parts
J27  3X7Inter  [SIP-27 2.54C]
J35  Vol_Sel  [SIP-3-2.54]

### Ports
3.3V_MicroP, 3.3VA_MicroP, 5V_MicroP, ADC0/IO19_MicroP (out), ADC1/IO20_MicroP (out), AGND, CS/IO9_MicroP (in), DAC/IO21_MicroP (bidir), GND, IO 2_MicroP (bidir), IO 3_MicroP (bidir), MISO/IO11_MicroP (out), MOSI/IO10_MicroP (in), PWM0/IO5_MicroP (in), PWM1/IO6_MicroP (in), RST_MicroP (in), RXD/IO15_MicroP (in), SCK/IO12_MicroP (in), SCL/IO18_MicroP (in), SDA/IO17_MicroP (bidir), TXD/IO16_MicroP (out)

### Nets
3.3V_MicroP: J27.26 ; port 3.3V_MicroP  [project net 3.3V]
3.3VA_MicroP: J35.3 ; port 3.3VA_MicroP  [project net 3.3V_6219]
5V/3.3VA_MicroP: J27.27 J35.2
5V_MicroP: J35.1 ; port 5V_MicroP  [project net 5V]
AGND: J27.1 ; port GND, port AGND  [also labelled GND]
ADC0/IO19_MicroP: J27.17 ; port ADC0/IO19_MicroP
ADC1/IO20_MicroP: J27.16 ; port ADC1/IO20_MicroP
CS/IO9_MicroP: J27.22 ; port CS/IO9_MicroP  [project net CS/GPIO7_Minip]
DAC/IO21_MicroP: J27.15 ; port DAC/IO21_MicroP
IO 2_MicroP: J27.11 ; port IO 2_MicroP  [project net GPIO14_Minip]
IO 3_MicroP: J27.10 ; port IO 3_MicroP  [project net GPIO11_Minip]
MISO/IO11_MicroP: J27.20 ; port MISO/IO11_MicroP
MOSI/IO10_MicroP: J27.21 ; port MOSI/IO10_MicroP  [project net MOSI/GPIO15_Minip]
PWM0/IO5_MicroP: J27.3 ; port PWM0/IO5_MicroP  [project net LM75_SCL]
PWM1/IO6_MicroP: J27.4 ; port PWM1/IO6_MicroP  [project net LM75_SDA]
RST_MicroP: J27.2 ; port RST_MicroP  [project net ~{RESET}]
RXD/IO15_MicroP: J27.9 ; port RXD/IO15_MicroP  [project net GPIO18_Minip]
SCK/IO12_MicroP: J27.19 ; port SCK/IO12_MicroP  [project net MISO/GPIO9_Minip]
SCL/IO18_MicroP: J27.12 ; port SCL/IO18_MicroP  [project net PA9/UART_TX/I2C_SCL]
SDA/IO17_MicroP: J27.13 ; port SDA/IO17_MicroP  [project net PA10/UART_RX/I2C_SDA]
TXD/IO16_MicroP: J27.8 ; port TXD/IO16_MicroP  [project net GPIO16_Minip]

Not connected (* = marked no-connect by the designer): J27 5 6 7 14 18 23 24 25

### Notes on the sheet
- (near J35) 物料代码:1.10.03.0164
- (near J35) 5V
- (near J35) Vmic
  3.3V
- GND
  RST
  PA11
  PA12
  NC
  NC
  NC
  PB6
  PB7
- TXD
- RXD
- 5V/3.3VA
  3.3V
  NC
  NC
  NC
  PA15
  PB5
  PB4
  PB3
- PA13
- PA14
- P
  A9
- PA10
- NC
- PA8
- PA0
- PA1
- VREF

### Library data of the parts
J27 = 3X7Inter: 物料代码: 1.10.11.0074
J35 = CON3: Connector; 物料代码: 1.10.03.0164

## Sheet 03.板载外设 BEEP PNP.SchDoc
size A4; CheckedBy: <审核日期>; CompanyName: 广州致远电子有限公司; DocumentNumber: 3; SheetNumber: 3; SheetTotal: 8; PageSetup: Record=PageOptions|CenterHorizontal=True|CenterVertical=True|PrintScale=1.00|XCorrection=1.00|YCorrection=1.00|PrintKind=0|BorderSize=5000000|LeftOffset=0|BottomOffset=0|Orientation=2|PaperLength=1000|PaperWidth=1000|Scale=100|PaperSource=7|PrintQuality=600|MediaType=1|DitherType=10|PaperKind=A4|PrintScaleMode=1; DesignDate: 20180913; CheckDate: <审核人员>; SheetName: 评估板外设; SheetVersion: V1.01; SheetDescription: 评估板外设; productModel: AML166-Core; productName: AML166
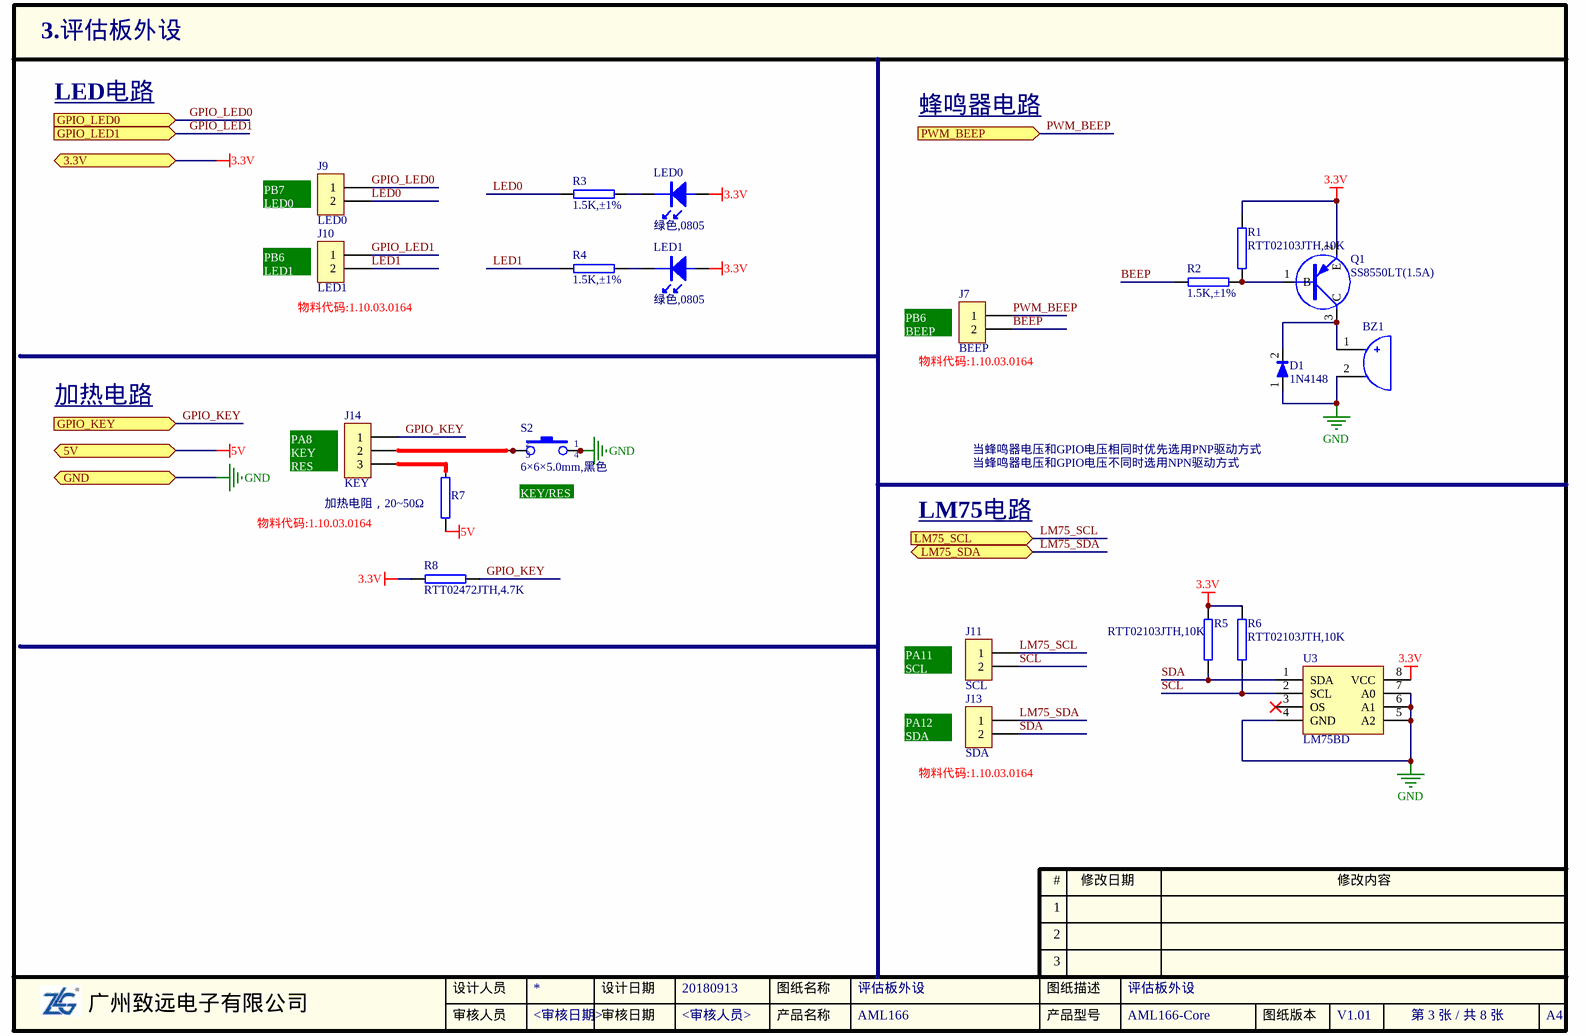
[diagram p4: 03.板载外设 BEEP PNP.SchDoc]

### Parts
BZ1  BUZZER2  [BUZZ-4/9]  (value not drawn)
D1  value 1N4148  [SOD-323]  (hidden comment: DIODE1)
J7  BEEP  [SIP-2-2.54]
J9  LED0  [SIP-2-2.54]
J10  LED1  [SIP-2-2.54]
J11  SCL  [SIP-2-2.54]
J13  SDA  [SIP-2-2.54]
J14  KEY  [SIP-3-2.54]
LED0  value 绿色,0805  [LED-0805]  (hidden comment: LED1)
LED1  value 绿色,0805  [LED-0805]  (hidden comment: LED1)
Q1  value SS8550LT(1.5A)  [SOT-23]  (hidden comment: PNP-1)
R1  RTT02103JTH,10K  [0402R]
R2  1.5K,±1%  [0402R]
R3  1.5K,±1%  [0402R]
R4  1.5K,±1%  [0402R]
R5  RTT02103JTH,10K  [0402R]
R6  RTT02103JTH,10K  [0402R]
R7  20Ω,±5%  [RESAD1778W80L1450D430P]  (value not drawn)
R8  RTT02472JTH,4.7K  [0402R]
S2  value 6×6×5.0mm,黑色  [KEY-6S]  (hidden comment: SW-PB4P)
U3  value LM75BD  [SOIC127P600X175-8N]  (hidden comment: LM75B)

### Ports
3.3V, 5V, GND, GPIO_KEY (in), GPIO_LED0 (in), GPIO_LED1 (in), LM75_SCL (in), LM75_SDA (bidir), PWM_BEEP (in)

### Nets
3.3V: LED0.1 LED1.1 Q1.2(E) R1.2 R5.2 R6.2 R8.1 U3.8(VCC) ; port 3.3V
5V: R7.1 ; port 5V
GND: BZ1.2(B) D1.1 S2.1 S2.4 U3.4(GND) U3.5(A2) U3.6(A1) U3.7(A0) ; port GND  [project net AGND]
BEEP: J7.2 R2.1
GPIO_KEY: J14.1 R8.2 ; port GPIO_KEY  [project net DAC/IO21_MicroP]
GPIO_LED0: J9.1 ; port GPIO_LED0  [project net GPIO18_Minip]
GPIO_LED1: J7.1 J10.1 ; port GPIO_LED1, port PWM_BEEP  [also labelled PWM_BEEP]  [project net GPIO16_Minip]
LED0: J9.2 R3.2
LED1: J10.2 R4.2
LM75_SCL: J11.1 ; port LM75_SCL
LM75_SDA: J13.1 ; port LM75_SDA
SCL: J11.2 R6.1 U3.2(SCL)
SDA: J13.2 R5.1 U3.1(SDA)
NetBZ1_1: BZ1.1(A) D1.2 Q1.3(C)
NetJ14_2: J14.2 S2.2 S2.3
NetJ14_3: J14.3 R7.2
NetLED0_2: LED0.2 R3.1
NetLED1_2: LED1.2 R4.1
NetQ1_1: Q1.1(B) R1.1 R2.2

Not connected (* = marked no-connect by the designer): U3 3(OS)*

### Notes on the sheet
- LED电路
- 蜂鸣器电路
- (near J9) PB7
  LED0
- (near J10) PB6
  LED1
- (near J10) 物料代码:1.10.03.0164
- (near J7) PB6
  BEEP
- (near J7) 物料代码:1.10.03.0164
- 加热电路
- (near J14) PA8
  KEY
  RES
- 加热电阻，20~50Ω
- (near S2) KEY/RES
- LM75电路
- 当蜂鸣器电压和GPIO电压相同时优先选用PNP驱动方式
- 当蜂鸣器电压和GPIO电压不同时选用NPN驱动方式
- 物料代码:1.10.03.0164
- PA11
  SCL
- PA12
  SDA
- (near J13) 物料代码:1.10.03.0164

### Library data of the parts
BZ1 = 1.06.09.0016: Buzzer有极性; Value: AS-905I-LF,无源; 名称: 讯响器; 厂商: 常州笠翔; 型号: AS-905I-LF,无源,Ф9×4.8mm; 贴片和直插: THT; PCB备注: Flq-Shcj-Twrj-150113; 器件优选方案: 量产物料,优先选用
D1 = 1.04.07.0027: 1N4148,SOD-323,RoHS; 名称: 二极管; 设备封装名称: SOD-323_1N4148; 贴片和直插: SMT
J7 J9-J11 J13 = CON2: Connector; 物料代码: 1.10.03.0164
J14 = CON3: Connector; 物料代码: 1.10.03.0164
LED0 LED1 = 1.04.05.0002: 绿色,0805,0805,RoHS; 名称: 发光二极管; 封装: 0805; 设备封装名称: LED0805-GREEN; 贴片和直插: SMT; 器件优选方案: 样品物料,谨慎选用
Q1 = 1.04.09.0002: PNP Transistor; 名称: 三极管; 设备封装名称: SOT-23_SS8550LT; 厂商: 江苏长电; 贴片和直插: SMT
R1 R5 R6 = 1.01.17.0006: as R11 on sheet 08.AML166
R2-R4 = 1.01.17.0011: 1.5K,±1%,0402,RALEC,RoHS; 名称: 电阻; 封装: 0402; 设备封装名称: R0402_1.5K_1%; 贴片和直插: SMT; 器件优选方案: 正常状态，可以选用
R7 = 1.01.10.0003: 20Ω,±5%,2W,Ф5.5×16mm,RoHS; 名称: 电阻; 贴片和直插: THT
R8 = 1.01.17.0019: RTT02472JTH,4.7K,±5%,0402,RALEC,RoHS; 名称: 电阻; 封装: 0402; 设备封装名称: R0402_4.7K; 贴片和直插: SMT; 器件优选方案: 正常状态，可以选用
S2 = 1.09.01.0003: as S4 on sheet 08.AML166
U3 = 1.05.10.0602: LM75BD,SO-9,NXP,RoHS; 名称: IC; 封装: SO-8; 贴片和直插: SMT; 器件优选方案: 样品物料,谨慎选用

## Sheet 02.Power.SchDoc
size A4; Author: 刘时杰; CompanyName: 广州致远电子有限公司; DocumentNumber: 2; SheetNumber: 2; SheetTotal: 8; PageSetup: Record=PageOptions|CenterHorizontal=True|CenterVertical=True|PrintScale=1.00|XCorrection=1.00|YCorrection=1.00|PrintKind=0|BorderSize=5000000|LeftOffset=0|BottomOffset=0|Orientation=2|PaperLength=1000|PaperWidth=1000|Scale=100|PaperSource=7|PrintQuality=600|MediaType=1|DitherType=10|PaperKind=A4|PrintScaleMode=1; DesignDate: 20180913; CheckDate: 20180913; SheetName: POWER; SheetVersion: V1.00; SheetDescription: AML166评估板电源电路
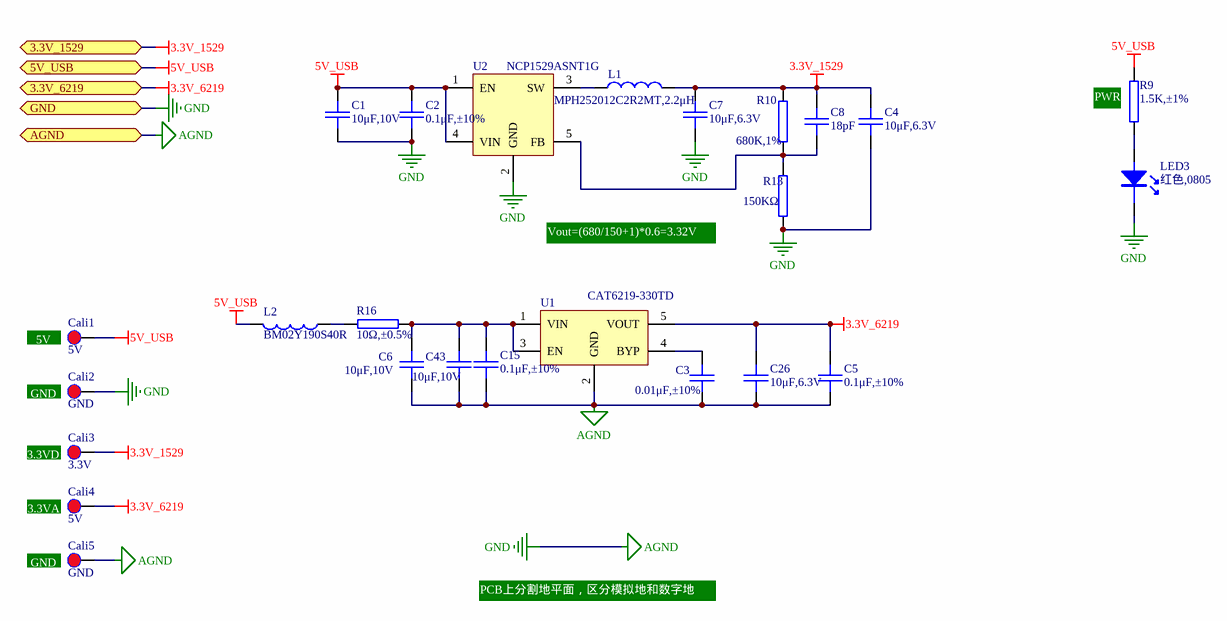
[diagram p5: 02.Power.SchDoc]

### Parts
C1  10μF,10V  [0805C]
C2  0.1μF,±10%  [0402C]
C3  0.01μF,±10%  [0402C]
C4  10μF,6.3V  [0603C]
C5  0.1μF,±10%  [0402C]
C6  10μF,10V  [0805C]
C7  10μF,6.3V  [0603C]
C8  18pF  [0402C]
C15  0.1μF,±10%  [0402C]
C26  10μF,6.3V  [0603C]
C43  10μF,10V  [0805C]
Cali1  5V  [PAD-25/40]  (no BOM)
Cali2  GND  [PAD-25/40]  (no BOM)
Cali3  3.3V  [PAD-25/40]  (no BOM)
Cali4  5V  [PAD-25/40]  (no BOM)
Cali5  GND  [PAD-25/40]  (no BOM)
L1  MPH252012C2R2MT,2.2μH  [INDC2520X10N]
L2  BM02Y190S40R  [0402RL]
LED3  value 红色,0805  [LED-0805]  (hidden comment: LED1)
R9  1.5K,±1%  [0402R]
R10  680K,1%  [0402R]
R13  150KΩ  [0603R]
R16  10Ω,±0.5%  [0402R]
U1  CAT6219-330TD  [SOT-23-5]
U2  NCP1529ASNT1G  [SOT-23-5]

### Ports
3.3V_1529, 3.3V_6219, 5V_USB, AGND, GND

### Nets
3.3V_1529: C4.1 C7.1 C8.1 Cali3.1 L1.2 R10.2 ; port 3.3V_1529  [project net 3.3V]
3.3V_6219: C5.1 C26.1 Cali4.1 U1.5(VOUT) ; port 3.3V_6219
5V_USB: C1.1 C2.1 Cali1.1 L2.2 R9.2 U2.1(EN) U2.4(VIN) ; port 5V_USB  [project net 5V]
AGND: C1.2 C2.2 C3.2 C4.2 C5.2 C6.2 C7.2 C15.2 C26.2 C43.2 Cali2.1 Cali5.1 LED3.2 R13.1 U1.2(GND) U2.2(GND) ; port GND, port AGND  [also labelled GND]
NetC3_1: C3.1 U1.4(BYP)
NetC6_1: C6.1 C15.1 C43.1 R16.2 U1.1(VIN) U1.3(EN)
NetC8_2: C8.2 R10.1 R13.2 U2.5(FB)
NetL1_1: L1.1 U2.3(SW)
NetL2_1: L2.1 R16.1
NetLED3_1: LED3.1 R9.1

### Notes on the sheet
- (near R9) PWR
- Vout=(680/150+1)*0.6=3.32V
- (near Cali1) 5V
- (near Cali2) GND
- (near Cali3) 3.3VD
- (near Cali4) 3.3VA
- (near Cali5) GND
- PCB上分割地平面，区分模拟地和数字地

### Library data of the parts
C1 C6 C43 = 1.02.02.0117: 10μF,±10%,10V,X7R,GRM21BR71A106KE51L,0805,muRata,RoHS; 名称: 电容; 封装: 0805; 贴片和直插: SMT; PCB备注: 171017lmd; 器件优选方案: 正常状态，可以选用
C2 C5 C15 = 1.02.17.0006: as C23 on sheet 08.AML166
C3 = 1.02.17.0019: as C39 on sheet 08.AML166
C4 C7 C26 = 1.02.01.0065: as C20 on sheet 08.AML166
C8 = 1.02.17.0078: GRM1555C1H180JA01D,18pF,±5%,50V,C0G,0402,muRata,RoHS; 名称: 电容; 封装: 0402; 贴片和直插: SMT; 器件优选方案: 正常状态，可以选用
Cali1-Cali5 = TEST-DOT
L1 = 1.03.01.0347: MPH252012C2R2MT,2.2μH,±20%,700mA,1008,Sunlord,RoHs; 名称: 电感; 封装: 1008; 贴片和直插: SMT; PCB备注: 160722ZW   160729toPCB-hcj; 器件优选方案: 正常状态，可以选用
L2 = 1.03.03.0022: BM02Y190S40R,0402,丰晶,RoHS; 名称: 磁珠; 封装: 0402; 贴片和直插: SMT; 器件优选方案: 正常状态，可以选用
LED3 = 1.04.05.0001: 红色,0805,0805,RoHS; 名称: 发光二极管; 封装: 0805; 设备封装名称: LED0805-RED; 贴片和直插: SMT; 器件优选方案: 样品物料,谨慎选用
R9 = 1.01.17.0011: as R2 on sheet 03.板载外设 BEEP PNP
R10 = 1.01.17.0086: 680K,1%,0402,Ralec,RoHS; 名称: 电阻; 封装: 0402; 贴片和直插: SMT; 器件优选方案: 正常状态，可以选用
R13 = 1.01.01.0065: 150KΩ,0603,*,RoHS; 名称: 电阻; 封装: 0603; 设备封装名称: R0603_150K; 厂商: Ralec; 贴片和直插: SMT; 器件优选方案: 正常状态，可以选用
R16 = 1.01.17.0049: 10Ω,±0.5%,0402,RoHS; 名称: 电阻; 封装: 0402; 设备封装名称: R0402_10R_0.5%; 厂商: Ralec; 贴片和直插: SMT; 器件优选方案: 正常状态，可以选用
U1 = 1.05.10.0321: CAT6219-330TD,TSOT-23-5,ON,RoHS; 名称: 集成电路; 设备封装名称: TSOT-23-5_CAT6219-330TD-GT3; 贴片和直插: SMT; 器件优选方案: 量产物料,优先选用
U2 = 1.05.09.0091: NCP1529ASNT1G,TSOP-5,ON,RoHS; 名称: 集成电路; 设备封装名称: TSOP-5_NCP1529ASNT1G; 贴片和直插: SMT; 器件优选方案: 量产物料,优先选用

## Sheet 09.RST_WDT_CAT823.SchDoc
size A4; CompanyName: 广州致远电子有限公司; DocumentNumber: 8; SheetNumber: 8; SheetTotal: 8; PageSetup: Record=PageOptions|CenterHorizontal=True|CenterVertical=True|PrintScale=1.00|XCorrection=1.00|YCorrection=1.00|PrintKind=0|BorderSize=5000000|LeftOffset=0|BottomOffset=0|Orientation=2|PaperLength=1000|PaperWidth=1000|Scale=100|PaperSource=7|PrintQuality=600|MediaType=1|DitherType=10|PaperKind=A4|PrintScaleMode=1; DesignDate: 2015-07-29; CheckDate: 2015-07-29; SheetName: CAT823; SheetVersion: V1.00; SheetDescription: CAT823
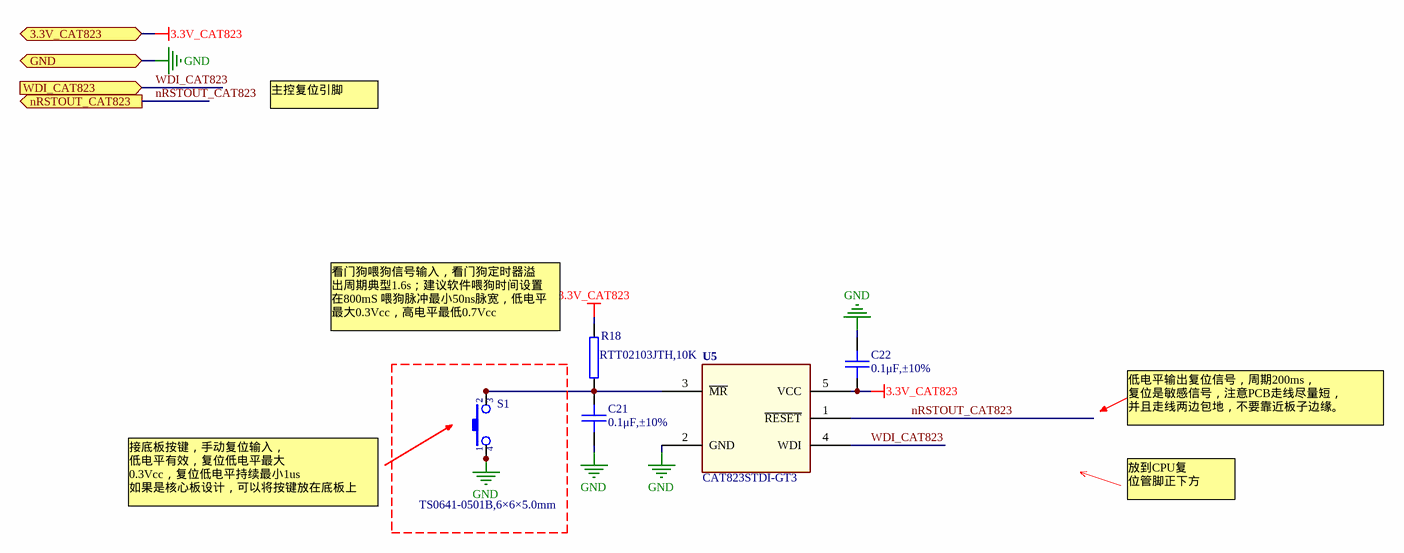
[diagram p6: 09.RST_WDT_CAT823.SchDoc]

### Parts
C21  0.1μF,±10%  [0402C]
C22  0.1μF,±10%  [0402C]
R18  RTT02103JTH,10K  [0402R]
S1  TS0641-0501B,6×6×5.0mm  [KEY-6S]
U5  CAT823STDI-GT3  [SOT-23-5]

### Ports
3.3V_CAT823, GND, nRSTOUT_CAT823 (out), WDI_CAT823 (in)

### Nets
3.3V_CAT823: C22.2 R18.1 U5.5(VCC) ; port 3.3V_CAT823  [project net 3.3V]
GND: C21.2 C22.1 S1.1 S1.4 U5.2(GND) ; port GND  [project net AGND]
nRSTOUT_CAT823: U5.1(~{RESET}) ; port nRSTOUT_CAT823  [project net nRST_WDT]
WDI_CAT823: U5.4(WDI) ; port WDI_CAT823  [project net GPIO14_Minip]
NetC21_1: C21.1 R18.2 S1.2 S1.3 U5.3(~{MR})

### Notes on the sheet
- 主控复位引脚
- (near R18) 看门狗喂狗信号输入，看门狗定时器溢
  出周期典型1.6s；建议软件喂狗时间设置
  在800mS 喂狗脉冲最小50ns脉宽，低电平
  最大0.3Vcc，高电平最低0.7Vcc
- 低电平输出复位信号，周期200ms，
  复位是敏感信号，注意PCB走线尽量短，
  并且走线两边包地，不要靠近板子边缘。
- 接底板按键，手动复位输入，
  低电平有效，复位低电平最大
  0.3Vcc，复位低电平持续最小1us
  如果是核心板设计，可以将按键放在底板上
- 放到CPU复
  位管脚正下方

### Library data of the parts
C21 C22 = 1.02.17.0006: as C23 on sheet 08.AML166
R18 = 1.01.17.0006: as R11 on sheet 08.AML166
S1 = 1.09.01.0003: TS0641-0501B,6×6×5.0mm,黑色,SMD,卷带装,RoHS; 名称: 轻触开关; 贴片和直插: SMT; 器件优选方案: 正常状态，可以选用
U5 = CAT823: 1.05.07.0025

## Sheet 07.USB Device_MicroUSB_CON.SchDoc
size A4; CompanyName: 广州致远电子有限公司; DocumentNumber: 6; SheetNumber: 6; SheetTotal: 8; PageSetup: Record=PageOptions|CenterHorizontal=True|CenterVertical=True|PrintScale=1.00|XCorrection=1.00|YCorrection=1.00|PrintKind=0|BorderSize=5000000|LeftOffset=0|BottomOffset=0|Orientation=2|PaperLength=1000|PaperWidth=1000|Scale=100|PaperSource=7|PrintQuality=600|MediaType=1|DitherType=10|PaperKind=A4|PrintScaleMode=1; DesignDate: 20180913; SheetName: USB接口电路; SheetVersion: <图纸版本>; SheetDescription: USB接口电路，纯供电，没有usb信号
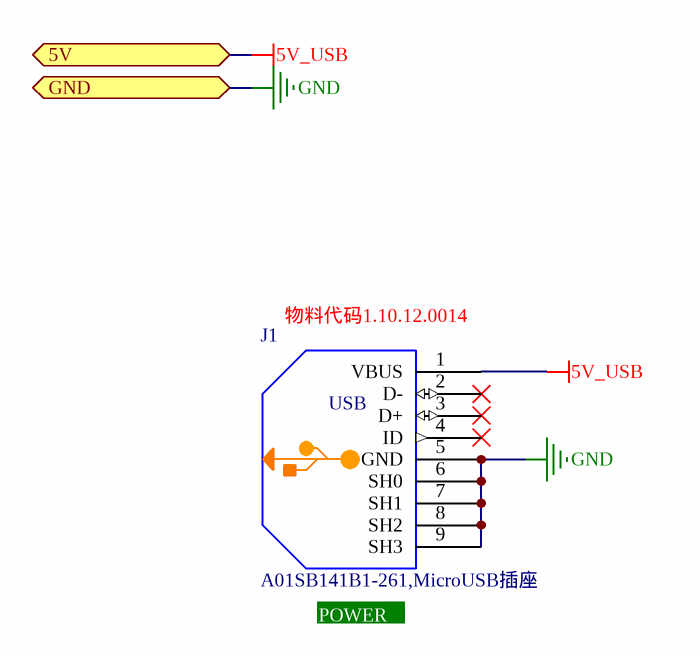
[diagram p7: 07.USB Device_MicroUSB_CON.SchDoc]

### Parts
J1  A01SB141B1-261,MicroUSB插座  [MICROUSB-5S]

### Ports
5V, GND

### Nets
5V_USB: J1.1(VBUS) ; port 5V  [project net 5V]
GND: J1.5(GND) J1.6(SH0) J1.7(SH1) J1.8(SH2) J1.9(SH3) ; port GND  [project net AGND]

Not connected (* = marked no-connect by the designer): J1 2(D-)* 3(D+)* 4(ID)*

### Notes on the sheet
- (near J1) 物料代码1.10.12.0014
- (near J1) POWER

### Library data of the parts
J1 = 1.10.12.0014: A01SB141B1-261,MicroUSB插座,SMT,艾立信,RoHS; PCB备注: 141030lmd; 器件优选方案: 正常状态，可以选用

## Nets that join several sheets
3.3V: 08.AML166 (10 pins), 05.Miniport_Host (J4.1), 04.Microport_Host (J27.26), 03.板载外设 BEEP PNP (8 pins), 02.Power (6 pins), 09.RST_WDT_CAT823 (C22.2 R18.1 U5.5)
3.3V_6219: 08.AML166 (12 pins), 04.Microport_Host (J35.3), 02.Power (C5.1 C26.1 Cali4.1 U1.5)
5V: 05.Miniport_Host (J4.2), 04.Microport_Host (J35.1), 03.板载外设 BEEP PNP (R7.1), 02.Power (7 pins), 07.USB Device_MicroUSB_CON (J1.1)
AGND: 01.mian (J26.1), 08.AML166 (43 pins), 05.Miniport_Host (J4.3 J4.4), 04.Microport_Host (J27.1), 03.板载外设 BEEP PNP (8 pins), 02.Power (16 pins), 09.RST_WDT_CAT823 (5 pins), 07.USB Device_MicroUSB_CON (5 pins)
ADC0/IO19_MicroP: 08.AML166 (U6.9), 05.Miniport_Host (J4.6), 04.Microport_Host (J27.17)
ADC1/IO20_MicroP: 08.AML166 (U6.8), 05.Miniport_Host (J4.5), 04.Microport_Host (J27.16)
ADC1_0: 01.mian (J15.1), 08.AML166 (R14.1)
ADC1_1: 01.mian (J15.2), 08.AML166 (R17.1)
CS/GPIO7_Minip: 08.AML166 (U6.26), 05.Miniport_Host (J4.7), 04.Microport_Host (J27.22)
DAC/IO21_MicroP: 08.AML166 (U6.18), 05.Miniport_Host (J4.8), 04.Microport_Host (J27.15), 03.板载外设 BEEP PNP (J14.1 R8.2)
GPIO11_Minip: 08.AML166 (J2.2 R11.1 U6.23), 05.Miniport_Host (J4.11), 04.Microport_Host (J27.10)
GPIO14_Minip: 08.AML166 (J2.3 R12.2 U6.25), 05.Miniport_Host (J4.14), 04.Microport_Host (J27.11), 09.RST_WDT_CAT823 (U5.4)
GPIO16_Minip: 08.AML166 (U6.30), 05.Miniport_Host (J4.16), 04.Microport_Host (J27.8), 03.板载外设 BEEP PNP (J7.1 J10.1)
GPIO18_Minip: 08.AML166 (U6.31), 05.Miniport_Host (J4.18), 04.Microport_Host (J27.9), 03.板载外设 BEEP PNP (J9.1)
LM75_SCL: 08.AML166 (U6.21), 05.Miniport_Host (J4.17), 04.Microport_Host (J27.3), 03.板载外设 BEEP PNP (J11.1)
LM75_SDA: 08.AML166 (U6.22), 05.Miniport_Host (J4.19), 04.Microport_Host (J27.4), 03.板载外设 BEEP PNP (J13.1)
MISO/GPIO9_Minip: 08.AML166 (U6.27), 05.Miniport_Host (J4.9), 04.Microport_Host (J27.19)
MISO/IO11_MicroP: 08.AML166 (U6.28), 05.Miniport_Host (J4.13), 04.Microport_Host (J27.20)
MOSI/GPIO15_Minip: 08.AML166 (U6.29), 05.Miniport_Host (J4.15), 04.Microport_Host (J27.21)
nRST_WDT: 08.AML166 (J8.1), 09.RST_WDT_CAT823 (U5.1)
PA9/UART_TX/I2C_SCL: 08.AML166 (U6.19), 05.Miniport_Host (J4.12), 04.Microport_Host (J27.12)
PA10/UART_RX/I2C_SDA: 08.AML166 (U6.20), 05.Miniport_Host (J4.10), 04.Microport_Host (J27.13)
~{RESET}: 08.AML166 (5 pins), 04.Microport_Host (J27.2)
RTD_A: 01.mian (J6.3), 08.AML166 (J5.3 R25.2)
RTD_B: 01.mian (J6.2), 08.AML166 (J12.3)
RTD_C: 01.mian (J6.1), 08.AML166 (J17.3 R24.1 R30.1 R49.2)
TC_A: 01.mian (J3.2), 08.AML166 (J5.1 R20.1)
TC_B: 01.mian (J3.1), 08.AML166 (J17.1 R43.1 R44.1)
VLDO: 01.mian (J26.2), 08.AML166 (C20.1 R22.2 U6.10)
